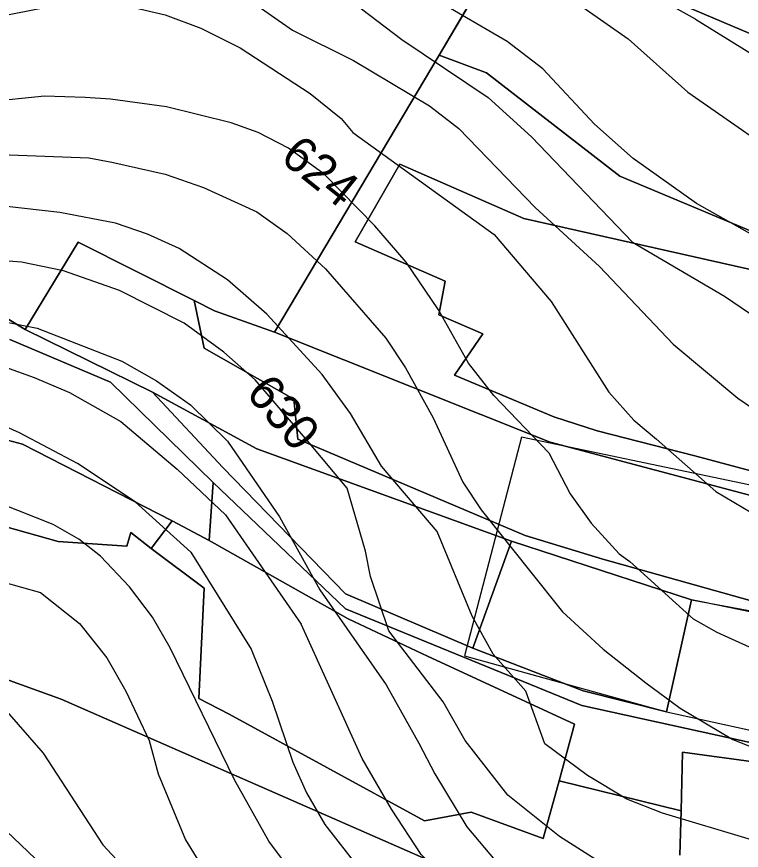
# Model space of a CAD drawing. Extents: x -709418 to -703832, y -1161719 to -1157826.
# Drawn here: x -707333 to -707168.1, y -1160311.5 to -1160121.7 of the extents above; entities that cross this region are included whole.
import ezdxf

# ---------------------------------------------------------------- set-up
doc = ezdxf.new("R2010")
doc.units = 0
for name, color, linetype in [('102_obvod PÚ', 7, 'Continuous'), ('106_zastavitelné plochy', 7, 'Continuous'), ('120_vrstevnice hlavní', 7, 'Continuous'), ('121_vrstevnice hlavní_popis', 7, 'Continuous'), ('122_vrstevnice základní', 7, 'Continuous'), ('204_zahrada_KN', 7, 'Continuous'), ('206_TTP_KN', 7, 'Continuous'), ('207_lesní pozemek_KN', 7, 'Continuous'), ('210_ostatní plocha_KN', 7, 'Continuous')]:
    doc.layers.add(name, color=color, linetype=linetype)

msp = doc.modelspace()

# ---------------------------------------------------------------- linework, layer by layer
at = {"layer": '102_obvod PÚ'}
msp.add_lwpolyline([(-707154.7, -1160259.5), (-707179.46, -1160254.43), (-707185.1, -1160279.91), (-707159.48, -1160285.54)], dxfattribs=at)
at = {"layer": '106_zastavitelné plochy'}
msp.add_lwpolyline([(-707218.12, -1160217.44), (-707231.07, -1160267.18), (-707185.1, -1160279.91), (-707179.46, -1160254.43), (-707123.8, -1160264.78), (-707121.16, -1160237.73), (-707218.12, -1160217.44)], dxfattribs=at)
at = {"layer": '120_vrstevnice hlavní'}
for points in [[(-707463.84, -1160165.44), (-707454.01, -1160157.37), (-707434.56, -1160148.21), (-707418.36, -1160142.56), (-707405.34, -1160139.09), (-707392.32, -1160134.46), (-707372.79, -1160125.93), (-707348.06, -1160116.53), (-707328.82, -1160107.99), (-707320.58, -1160105.68), (-707312.48, -1160104.96), (-707304.96, -1160105.54), (-707294.54, -1160108.86), (-707287.6, -1160112.62), (-707270.24, -1160124.77), (-707256.35, -1160131.72), (-707239, -1160141.99), (-707232.34, -1160147.19), (-707214.99, -1160165.13), (-707200.36, -1160178.58)], [(-707257.8, -1160229.06), (-707266.37, -1160218.79), (-707278.72, -1160204.35), (-707285.86, -1160198.11), (-707294.83, -1160191.45), (-707309.58, -1160184.08), (-707322.31, -1160179.59), (-707331.86, -1160177.57), (-707347.77, -1160176.41), (-707366.86, -1160177.57), (-707390.01, -1160183.93), (-707397.09, -1160186.97)], [(-707200.36, -1160178.58), (-707183.6, -1160196.23), (-707168.85, -1160208.52), (-707163.64, -1160212.14), (-707149.32, -1160219.52), (-707110.26, -1160232.82), (-707097.25, -1160238.46), (-707074.39, -1160250.61), (-707060.65, -1160259.44), (-707056.47, -1160265.22), (-707056.72, -1160271.75), (-707043.58, -1160281.57), (-707040.29, -1160286.17), (-707036.39, -1160293.38), (-707032.35, -1160302.26), (-707030.28, -1160309.28)], [(-707235.96, -1160277.66), (-707248.31, -1160261.52), (-707252.45, -1160249.17), (-707253.61, -1160243.38), (-707257.8, -1160229.06)], [(-707336.2, -1160250.32), (-707327.52, -1160252.78), (-707318.7, -1160259.87), (-707312.48, -1160267.68), (-707308.14, -1160275.2), (-707302.79, -1160286.49), (-707300.76, -1160294.01), (-707294.54, -1160309.05), (-707289.91, -1160316.57), (-707287.16, -1160319.9), (-707278.05, -1160328.58), (-707243.48, -1160350.13), (-707214.36, -1160373.39)], [(-707086.69, -1160357.22), (-707101.31, -1160345.23), (-707118.07, -1160337.4), (-707133.12, -1160333.06), (-707157.71, -1160326.99), (-707172.46, -1160324.09), (-707187.21, -1160320.04), (-707196.91, -1160316.28), (-707209.49, -1160308.33), (-707221.21, -1160298.93), (-707230.9, -1160286.49), (-707235.96, -1160277.66)]]:
    msp.add_lwpolyline(points, dxfattribs=at)
at = {"layer": '122_vrstevnice základní'}
for points in [[(-707178.54, -1160122.31), (-707224.08, -1160096.9), (-707236.78, -1160085.44), (-707252.02, -1160072.7), (-707263.59, -1160065.9), (-707276.32, -1160060.7), (-707293.67, -1160056.65), (-707317.1, -1160054.33), (-707328.39, -1160054.62), (-707351.82, -1160056.94), (-707370.05, -1160060.41), (-707387.98, -1160065.32), (-707403.6, -1160070.82), (-707413.58, -1160075.02), (-707418.36, -1160076.46), (-707444.97, -1160084.27), (-707462.33, -1160090.64), (-707480.84, -1160098.3), (-707489.52, -1160102.79), (-707500.8, -1160110.89), (-707517.87, -1160121.88), (-707543.18, -1160141.12)], [(-707483.93, -1160158.93), (-707464.79, -1160146.47), (-707450.76, -1160139.96), (-707408.67, -1160124.34), (-707398.11, -1160121.16), (-707376.12, -1160113.2), (-707369.32, -1160110.89), (-707345.74, -1160102.35), (-707323.18, -1160093.24), (-707314.79, -1160091.36), (-707306.11, -1160090.93), (-707297.14, -1160092.23), (-707287.31, -1160097), (-707265.61, -1160111.47), (-707245.36, -1160126.94), (-707225.69, -1160140.1), (-707215.85, -1160149.07), (-707192.85, -1160173.08), (-707171.93, -1160185.32)], [(-707228.15, -1160106.11), (-707204.14, -1160119.57), (-707193.87, -1160126.8), (-707180.27, -1160138.95), (-707162.62, -1160151.24), (-707144.11, -1160162.96), (-707136.44, -1160167.15), (-707127.91, -1160170.92), (-707107.95, -1160177.57), (-707101.73, -1160180.17), (-707076.27, -1160194.35), (-707068.9, -1160199.99), (-707059.64, -1160207.08), (-707046.91, -1160218.36), (-707041.41, -1160222.26), (-707036.62, -1160225.88), (-707032.82, -1160228.1), (-707029, -1160229.65)], [(-707122.56, -1160186.39), (-707154.96, -1160179.3), (-707163.06, -1160172.8), (-707178.25, -1160164.26), (-707192.71, -1160153.99), (-707201.53, -1160146.18), (-707213.25, -1160133.6), (-707221.35, -1160127.38), (-707237.55, -1160117.98)], [(-707455.2, -1160168.65), (-707446.27, -1160162.38), (-707436.15, -1160157.32), (-707391.74, -1160141.12), (-707377.13, -1160136.63), (-707337.5, -1160121.74), (-707322.31, -1160118.84), (-707315.95, -1160118.55), (-707307.27, -1160119.42), (-707299.17, -1160121.3), (-707291.07, -1160124.34), (-707282.1, -1160128.82), (-707266.19, -1160139.24), (-707259.1, -1160144.88), (-707256.5, -1160148.06), (-707224.3, -1160171.28)], [(-707178.54, -1160122.31), (-707166.39, -1160129.84), (-707155.68, -1160135.48), (-707144.98, -1160139.67), (-707136.88, -1160141.84), (-707120.68, -1160144.45), (-707107.95, -1160149.8), (-707096.23, -1160157.75), (-707064.89, -1160183.61), (-707057.44, -1160187.88), (-707050.94, -1160188.3), (-707045.92, -1160187.2), (-707042.22, -1160184.58), (-707039.34, -1160181.12), (-707038.1, -1160175.96), (-707037.5, -1160168.63), (-707037.81, -1160161.26), (-707030.76, -1160157.83)], [(-707211.9, -1160221.01), (-707224.39, -1160207.94), (-707230.17, -1160200.57), (-707236.97, -1160188.42), (-707244.35, -1160177.57), (-707251.44, -1160169.32), (-707263.01, -1160157.61), (-707271.11, -1160151.68), (-707278.05, -1160148.06), (-707284.13, -1160145.89), (-707298.88, -1160142.28), (-707311.61, -1160140.54), (-707317.39, -1160140.1), (-707326.65, -1160139.82), (-707353.27, -1160142.56), (-707371.78, -1160145.46), (-707407.65, -1160154.86), (-707418.07, -1160158.33), (-707430.8, -1160164.98), (-707438.61, -1160170.77), (-707442.51, -1160172.94)], [(-707426.38, -1160176.36), (-707416.8, -1160169.76), (-707402.73, -1160162.96), (-707395.21, -1160159.92), (-707384.8, -1160156.88), (-707372.07, -1160154.43), (-707355, -1160152.83), (-707346.76, -1160152.69), (-707316.53, -1160153.85), (-707311.32, -1160154.86), (-707299.17, -1160157.61), (-707290.49, -1160160.65), (-707278.34, -1160166.14), (-707271.4, -1160171.06), (-707262.72, -1160179.16), (-707248.98, -1160194.93), (-707244.47, -1160201.67), (-707238.18, -1160213.02)], [(-707237.26, -1160238.9), (-707249.98, -1160224.04), (-707257.04, -1160212.05), (-707263.44, -1160203.17), (-707276.03, -1160189.43), (-707284.99, -1160181.62), (-707295.99, -1160174.53), (-707303.22, -1160171.2), (-707310.45, -1160168.75), (-707323.18, -1160166.29), (-707335.91, -1160164.84), (-707356.74, -1160164.7), (-707367.15, -1160165.27), (-707377.57, -1160167.01), (-707385.67, -1160169.18), (-707413, -1160181.19)], [(-707224.3, -1160171.28), (-707211.37, -1160186.54), (-707198.21, -1160207.22), (-707192.57, -1160213.58), (-707187.36, -1160217.92), (-707173.89, -1160229.82)], [(-707171.93, -1160185.32), (-707152.93, -1160198.25), (-707146.14, -1160201.87), (-707136.01, -1160205.2), (-707123.86, -1160207.51), (-707111.71, -1160210.69), (-707101.59, -1160214.16), (-707087.41, -1160220.24), (-707070.49, -1160230.51), (-707058.19, -1160240.2), (-707044.08, -1160256.43), (-707033.93, -1160269.23), (-707029.68, -1160275.28), (-707025.1, -1160281.33), (-707020.67, -1160286.06), (-707017.03, -1160287.77), (-707012.11, -1160288.36), (-707005.71, -1160288.09), (-707003.18, -1160285.96), (-707001.47, -1160282.49), (-707001.22, -1160276.33), (-707001.69, -1160264.81), (-706995.49, -1160261.9), (-706993, -1160250.04)], [(-707379.91, -1160193.11), (-707363.78, -1160190.01), (-707351.5, -1160189.68), (-707340.72, -1160190.16), (-707328.31, -1160192.65), (-707309.01, -1160200.13), (-707301.19, -1160204.62), (-707293.38, -1160210.11), (-707284.99, -1160218.36), (-707273.13, -1160235.57), (-707264.02, -1160252.21), (-707248.93, -1160273.83)], [(-707358.62, -1160199.31), (-707346.85, -1160199.63), (-707336.6, -1160201.09), (-707329.01, -1160203.85), (-707320.93, -1160207.27), (-707309.24, -1160213.9), (-707296.46, -1160224.68), (-707285.49, -1160235.11), (-707268.22, -1160260.02)], [(-707293.35, -1160243.63), (-707306.02, -1160232.18), (-707319.15, -1160223.39), (-707332.32, -1160216.42), (-707343.02, -1160211.63), (-707353.94, -1160210.49), (-707363.41, -1160212.49), (-707372.12, -1160216.25), (-707379.13, -1160219.81), (-707387.49, -1160225.33), (-707400.23, -1160236.26), (-707410.3, -1160245.07)], [(-707238.18, -1160213.02), (-707231.46, -1160227.64), (-707227.28, -1160233.98), (-707216.25, -1160247.81)], [(-707211.9, -1160221.01), (-707207.03, -1160230.36), (-707202.26, -1160237.02), (-707195.89, -1160243.96), (-707193.43, -1160245.7), (-707178.97, -1160258.86)], [(-707173.89, -1160229.82), (-707161.58, -1160237.08), (-707155.1, -1160240.06), (-707126.17, -1160248.73), (-707072.66, -1160271.59), (-707060.51, -1160278.1), (-707048.93, -1160286.05), (-707043.39, -1160294.11), (-707039.03, -1160303.32), (-707032.8, -1160318.33), (-707030.42, -1160326.35)], [(-707197.63, -1160382.39), (-707206.27, -1160368.55), (-707228.73, -1160349.26), (-707246.81, -1160337.98), (-707255.78, -1160331.32), (-707267.35, -1160320.48), (-707275.59, -1160309.34), (-707283.4, -1160295.45), (-707298.01, -1160265.37), (-707302.06, -1160258.43), (-707307.27, -1160251.48), (-707313.92, -1160244.54), (-707318.84, -1160240.63), (-707324.63, -1160237.31), (-707336.78, -1160232.53), (-707341.98, -1160231.09), (-707348.93, -1160230.22), (-707357.66, -1160231.62), (-707366.59, -1160234.24), (-707374.93, -1160238.93), (-707384.3, -1160245.93), (-707391.5, -1160251.96)], [(-707212.82, -1160287.21), (-707217.1, -1160275.22), (-707224.53, -1160266.81), (-707229.31, -1160258.14), (-707237.26, -1160238.9)], [(-707293.35, -1160243.63), (-707279.65, -1160265.66), (-707274.87, -1160277.52), (-707270.1, -1160291.4), (-707267.06, -1160298.35), (-707262.86, -1160305.58), (-707255.05, -1160315.56), (-707248.83, -1160321.92), (-707241.74, -1160327.56), (-707214.99, -1160345.21), (-707206.31, -1160352.01), (-707190.54, -1160366.18), (-707176.37, -1160380.36), (-707169.06, -1160392.35)], [(-707216.25, -1160247.81), (-707208.81, -1160257.2), (-707199.51, -1160265.66), (-707189.82, -1160273.32), (-707182.01, -1160279.11), (-707170, -1160286.2), (-707159.15, -1160290.54), (-707147.58, -1160293.57), (-707102.45, -1160298.78), (-707093.77, -1160300.81), (-707085.1, -1160303.84), (-707078.88, -1160306.74), (-707059.64, -1160319.18), (-707053.71, -1160325.83), (-707046.47, -1160335.67), (-707040.84, -1160347.05), (-707036.98, -1160356.57), (-707033.79, -1160366.42), (-707031, -1160381.41), (-707032.56, -1160386.71), (-707026.38, -1160395.27)], [(-707205.2, -1160336.94), (-707225.52, -1160325.91), (-707233.56, -1160319.66), (-707240.92, -1160312.43), (-707247.68, -1160302.11), (-707254.33, -1160290.54), (-707268.22, -1160260.02)], [(-707009.56, -1160420.55), (-707013.67, -1160417.17), (-707015.1, -1160412), (-707016.15, -1160403.5), (-707018.79, -1160390.33), (-707020.84, -1160381.99), (-707021.89, -1160373.85), (-707025.49, -1160344.4), (-707030.48, -1160344.5), (-707033.85, -1160335.48), (-707040, -1160323.09), (-707050.09, -1160307.03), (-707055.44, -1160300.08), (-707059.06, -1160296.9), (-707073.96, -1160288.08), (-707081.05, -1160284.6), (-707092.62, -1160280.27), (-707107.08, -1160277.23), (-707127.33, -1160275.64), (-707141.8, -1160273.47), (-707150.47, -1160271.3), (-707162.05, -1160267.1), (-707173.62, -1160261.9), (-707178.97, -1160258.86)], [(-707442.94, -1160342.52), (-707442.45, -1160332.85), (-707434.12, -1160319.18), (-707426.17, -1160310.93), (-707420.38, -1160306.45), (-707411.7, -1160301.96), (-707389.43, -1160292.13), (-707382.05, -1160287.64), (-707371.35, -1160279.11), (-707364.84, -1160275.49), (-707358.18, -1160273.32), (-707351.24, -1160272.89), (-707343.72, -1160274.33), (-707335.76, -1160279.25), (-707326.94, -1160289.38), (-707313.34, -1160310.21), (-707298.01, -1160326.7), (-707289.62, -1160332.63), (-707277.47, -1160338.27), (-707267.78, -1160341.88), (-707240.48, -1160362.57)], [(-707248.93, -1160273.83), (-707241.46, -1160287.06), (-707237.84, -1160294.01), (-707230.52, -1160306.13), (-707222.5, -1160315.67), (-707215.45, -1160321.9), (-707206.24, -1160328.16), (-707195.21, -1160333.95)], [(-707141.04, -1160312.04), (-707153.66, -1160311.36), (-707165.81, -1160309.05), (-707186.06, -1160302.98), (-707194.16, -1160299.79), (-707203.12, -1160294.44), (-707212.82, -1160287.21)], [(-707399.99, -1160324.96), (-707391.42, -1160316.4), (-707374.78, -1160305.88), (-707360.5, -1160299.65), (-707351.82, -1160298.64), (-707346.74, -1160298.97), (-707341.98, -1160300.81), (-707318.84, -1160322.79), (-707307.41, -1160331.76), (-707261.99, -1160355.77)]]:
    msp.add_lwpolyline(points, dxfattribs=at)
at = {"layer": '204_zahrada_KN'}
for p, q in [((-707236.82, -1160130.53), (-707220.33, -1160102.45)), ((-707220.33, -1160102.45), (-707150.38, -1160132.32)), ((-707226.04, -1160134.55), (-707236.82, -1160130.53)), ((-707195.71, -1160158.06), (-707226.04, -1160134.55)), ((-707165.88, -1160170.52), (-707195.71, -1160158.06)), ((-707292.59, -1160186.35), (-707287.95, -1160188.66)), ((-707290.31, -1160197.16), (-707292.59, -1160186.35)), ((-707287.95, -1160188.66), (-707274.29, -1160193.52)), ((-707274.29, -1160193.52), (-707211.57, -1160218.56)), ((-707269.91, -1160208.82), (-707290.31, -1160197.16)), ((-707269.01, -1160217.88), (-707269.91, -1160208.82)), ((-707217.26, -1160239.81), (-707269.01, -1160217.88)), ((-707211.57, -1160218.56), (-707156.55, -1160233.24)), ((-707199.62, -1160245.21), (-707217.26, -1160239.81)), ((-707154.02, -1160257.98), (-707199.62, -1160245.21))]:
    msp.add_line(p, q, dxfattribs=at)
at = {"layer": '206_TTP_KN'}
for p, q in [((-707255.98, -1160172.97), (-707245.78, -1160155.27)), ((-707245.78, -1160155.27), (-707217.59, -1160167.68)), ((-707217.59, -1160167.68), (-707147.54, -1160183.41)), ((-707235.49, -1160181.92), (-707255.98, -1160172.97)), ((-707236.92, -1160189.56), (-707235.49, -1160181.92)), ((-707226.93, -1160193.91), (-707236.92, -1160189.56)), ((-707233.35, -1160203.33), (-707226.93, -1160193.91)), ((-707210.73, -1160212.82), (-707233.35, -1160203.33)), ((-707200.88, -1160215.96), (-707210.73, -1160212.82)), ((-707353.38, -1160213.44), (-707331.62, -1160219.01)), ((-707178.69, -1160221.67), (-707200.88, -1160215.96)), ((-707331.62, -1160219.01), (-707297.58, -1160236.49)), ((-707162.56, -1160226.02), (-707178.69, -1160221.67)), ((-707297.58, -1160236.49), (-707302.37, -1160242.77)), ((-707302.37, -1160242.77), (-707297.58, -1160236.49)), ((-707297.58, -1160236.49), (-707289.16, -1160240.91)), ((-707323.49, -1160241.2), (-707335.63, -1160237.76)), ((-707307, -1160239.13), (-707307.93, -1160242.27)), ((-707302.37, -1160242.77), (-707307, -1160239.13)), ((-707307.93, -1160242.27), (-707323.49, -1160241.2)), ((-707289.16, -1160240.91), (-707257.52, -1160258.76)), ((-707290.31, -1160251.76), (-707302.37, -1160242.77)), ((-707291.52, -1160276.88), (-707290.31, -1160251.76)), ((-707257.52, -1160258.76), (-707239.5, -1160267.25)), ((-707367.81, -1160260.92), (-707322.83, -1160277.04)), ((-707239.5, -1160267.25), (-707206.03, -1160282.77)), ((-707322.83, -1160277.04), (-707203.73, -1160329.24)), ((-707284.6, -1160280.45), (-707291.52, -1160276.88)), ((-707240.14, -1160304.71), (-707284.6, -1160280.45)), ((-707206.03, -1160282.77), (-707209.57, -1160295.61)), ((-707181.81, -1160302.5), (-707181.48, -1160289.09)), ((-707181.48, -1160289.09), (-707135.81, -1160295.36)), ((-707209.57, -1160295.61), (-707213.17, -1160308.78)), ((-707229.58, -1160302.79), (-707240.14, -1160304.71)), ((-707213.17, -1160308.78), (-707229.58, -1160302.79)), ((-707182.07, -1160312.58), (-707181.81, -1160302.5))]:
    msp.add_line(p, q, dxfattribs=at)
at = {"layer": '207_lesní pozemek_KN'}
for p, q in [((-707220.33, -1160102.45), (-707236.82, -1160130.53)), ((-707236.82, -1160130.53), (-707274.29, -1160193.52)), ((-707318.98, -1160173.09), (-707331.07, -1160192.93)), ((-707292.59, -1160186.35), (-707318.98, -1160173.09)), ((-707331.07, -1160192.93), (-707345.73, -1160183.99)), ((-707287.95, -1160188.66), (-707292.59, -1160186.35)), ((-707274.29, -1160193.52), (-707287.95, -1160188.66)), ((-707334.51, -1160195.21), (-707311.6, -1160204.91)), ((-707311.6, -1160204.91), (-707288.23, -1160227.75)), ((-707331.62, -1160219.01), (-707353.38, -1160213.44)), ((-707297.58, -1160236.49), (-707331.62, -1160219.01)), ((-707288.23, -1160227.75), (-707289.16, -1160240.91)), ((-707289.16, -1160240.91), (-707297.58, -1160236.49)), ((-707335.63, -1160237.76), (-707323.49, -1160241.2)), ((-707307.93, -1160242.27), (-707307, -1160239.13)), ((-707307, -1160239.13), (-707302.37, -1160242.77)), ((-707323.49, -1160241.2), (-707307.93, -1160242.27)), ((-707302.37, -1160242.77), (-707290.31, -1160251.76)), ((-707290.31, -1160251.76), (-707291.52, -1160276.88)), ((-707322.83, -1160277.04), (-707367.81, -1160260.92)), ((-707203.73, -1160329.24), (-707322.83, -1160277.04)), ((-707291.52, -1160276.88), (-707284.6, -1160280.45)), ((-707284.6, -1160280.45), (-707240.14, -1160304.71)), ((-707213.17, -1160308.78), (-707209.57, -1160295.61)), ((-707209.57, -1160295.61), (-707181.81, -1160302.5)), ((-707240.14, -1160304.71), (-707229.58, -1160302.79)), ((-707229.58, -1160302.79), (-707213.17, -1160308.78)), ((-707181.81, -1160302.5), (-707182.07, -1160312.58))]:
    msp.add_line(p, q, dxfattribs=at)
at = {"layer": '210_ostatní plocha_KN'}
for p, q in [((-707150.38, -1160132.32), (-707220.33, -1160102.45)), ((-707274.29, -1160193.52), (-707236.82, -1160130.53)), ((-707236.82, -1160130.53), (-707226.04, -1160134.55)), ((-707226.04, -1160134.55), (-707195.71, -1160158.06)), ((-707245.78, -1160155.27), (-707255.98, -1160172.97)), ((-707217.59, -1160167.68), (-707245.78, -1160155.27)), ((-707195.71, -1160158.06), (-707165.88, -1160170.52)), ((-707147.54, -1160183.41), (-707217.59, -1160167.68)), ((-707255.98, -1160172.97), (-707235.49, -1160181.92)), ((-707331.07, -1160192.93), (-707318.98, -1160173.09)), ((-707318.98, -1160173.09), (-707292.59, -1160186.35)), ((-707235.49, -1160181.92), (-707236.92, -1160189.56)), ((-707345.73, -1160183.99), (-707331.07, -1160192.93)), ((-707292.59, -1160186.35), (-707290.31, -1160197.16)), ((-707236.92, -1160189.56), (-707226.93, -1160193.91)), ((-707331.07, -1160192.93), (-707302.09, -1160207.18)), ((-707302.09, -1160207.18), (-707331.07, -1160192.93)), ((-707211.57, -1160218.56), (-707274.29, -1160193.52)), ((-707311.6, -1160204.91), (-707334.51, -1160195.21)), ((-707226.93, -1160193.91), (-707233.35, -1160203.33)), ((-707290.31, -1160197.16), (-707269.91, -1160208.82)), ((-707233.35, -1160203.33), (-707210.73, -1160212.82)), ((-707288.23, -1160227.75), (-707311.6, -1160204.91)), ((-707302.09, -1160207.18), (-707286.05, -1160224.32)), ((-707278.35, -1160220.11), (-707302.09, -1160207.18)), ((-707302.09, -1160207.18), (-707278.35, -1160220.11)), ((-707286.05, -1160224.32), (-707302.09, -1160207.18)), ((-707269.91, -1160208.82), (-707269.01, -1160217.88)), ((-707210.73, -1160212.82), (-707200.88, -1160215.96)), ((-707200.88, -1160215.96), (-707178.69, -1160221.67)), ((-707269.01, -1160217.88), (-707217.26, -1160239.81)), ((-707220.39, -1160241.08), (-707278.35, -1160220.11)), ((-707278.35, -1160220.11), (-707220.39, -1160241.08)), ((-707156.55, -1160233.24), (-707211.57, -1160218.56)), ((-707178.69, -1160221.67), (-707162.56, -1160226.02)), ((-707286.05, -1160224.32), (-707258.15, -1160253.08)), ((-707258.15, -1160253.08), (-707286.05, -1160224.32)), ((-707289.16, -1160240.91), (-707288.23, -1160227.75)), ((-707258.17, -1160256.49), (-707288.23, -1160227.75)), ((-707288.23, -1160227.75), (-707258.17, -1160256.49)), ((-707257.52, -1160258.76), (-707289.16, -1160240.91)), ((-707220.39, -1160241.08), (-707229.16, -1160265.48)), ((-707229.16, -1160265.48), (-707220.39, -1160241.08)), ((-707179.46, -1160254.43), (-707220.39, -1160241.08)), ((-707220.39, -1160241.08), (-707179.46, -1160254.43)), ((-707217.26, -1160239.81), (-707199.62, -1160245.21)), ((-707199.62, -1160245.21), (-707154.02, -1160257.98)), ((-707258.15, -1160253.08), (-707229.16, -1160265.48)), ((-707229.16, -1160265.48), (-707258.15, -1160253.08)), ((-707179.46, -1160254.43), (-707185.1, -1160279.91)), ((-707154.7, -1160259.5), (-707179.46, -1160254.43)), ((-707204.36, -1160278.47), (-707258.17, -1160256.49)), ((-707258.17, -1160256.49), (-707204.36, -1160278.47)), ((-707239.5, -1160267.25), (-707257.52, -1160258.76)), ((-707229.16, -1160265.48), (-707204.08, -1160275.19)), ((-707204.08, -1160275.19), (-707229.16, -1160265.48)), ((-707206.03, -1160282.77), (-707239.5, -1160267.25)), ((-707204.08, -1160275.19), (-707185.1, -1160279.91)), ((-707185.1, -1160279.91), (-707204.08, -1160275.19)), ((-707121.9, -1160296.72), (-707204.36, -1160278.47)), ((-707204.36, -1160278.47), (-707121.9, -1160296.72)), ((-707185.1, -1160279.91), (-707159.48, -1160285.54)), ((-707209.57, -1160295.61), (-707206.03, -1160282.77)), ((-707181.48, -1160289.09), (-707181.81, -1160302.5)), ((-707135.81, -1160295.36), (-707181.48, -1160289.09)), ((-707181.81, -1160302.5), (-707209.57, -1160295.61))]:
    msp.add_line(p, q, dxfattribs=at)

# ---------------------------------------------------------------- texts
at = {"layer": '121_vrstevnice hlavní_popis'}
for s, rotation, p in [('624', 321.1944, (-707273.29, -1160154.38)), ('630', 310.2206, (-707281.05, -1160207.51))]:
    msp.add_text(s, height=8, rotation=rotation, dxfattribs=at).set_placement(p)

doc.saveas('drawing.dxf')
